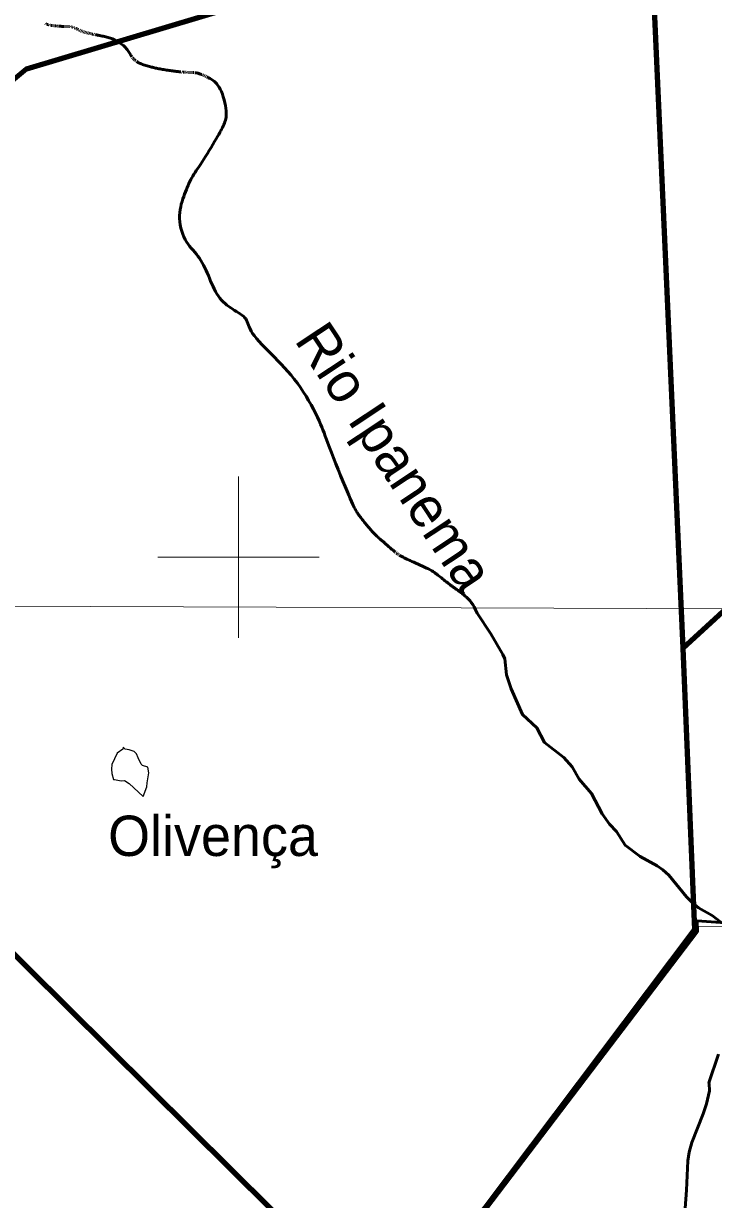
# Model space of a CAD drawing. Extents: x -1643653 to 4543381, y 1624270 to 13878484.
# Drawn here: x 697335 to 705888, y 8942036 to 8956618 of the extents above; entities that cross this region are included whole.
import ezdxf
from ezdxf.enums import TextEntityAlignment as Align

# ---------------------------------------------------------------- set-up
doc = ezdxf.new("R2010")
doc.units = 0
doc.header["$LTSCALE"] = 200
for name, color, linetype, lineweight in [('1', 7, 'Continuous', 13), ('2', 7, 'Continuous', 13), ('21', 7, 'Continuous', 25), ('24', 7, 'Continuous', 25), ('58', 7, 'Continuous', 13), ('59', 7, 'Continuous', 53), ('60', 7, 'Continuous', 13), ('9', 7, 'Continuous', 90)]:
    doc.layers.add(name, color=color, linetype=linetype, lineweight=lineweight)
doc.layers.add('41', color=7, linetype='Continuous')
doc.layers.add('49', color=7, linetype='Continuous')

msp = doc.modelspace()

# ---------------------------------------------------------------- linework, layer by layer
at = {"layer": '1'}
msp.add_line((565315.3, 8949866.8), (791497.7, 8949052.2), dxfattribs=at)
at = {"layer": '2'}
for p, q in [((700000, 8949000), (700000, 8951000)), ((699000, 8950000), (701000, 8950000))]:
    msp.add_line(p, q, dxfattribs=at)
at = {"layer": '21'}
for points in [[(698875, 8947397.9), (698811.7, 8947415.6), (698794.2, 8947433.6), (698754.7, 8947514.3), (698737.5, 8947564.1), (698706.2, 8947592.7), (698643, 8947613), (698593.3, 8947619.9), (698571.6, 8947643.2), (698565.2, 8947619.3), (698494.7, 8947572.1), (698431.7, 8947429.7), (698426.6, 8947373.4), (698428.3, 8947318.5), (698449.3, 8947244.8)], [(698819.7, 8947032.6), (698863.9, 8947152.1), (698866.6, 8947202.8), (698888.3, 8947328.1), (698875, 8947397.9)], [(698449.3, 8947244.8), (698461.1, 8947244.4), (698543.5, 8947225.9), (698588, 8947231.3), (698646.7, 8947194.3), (698819.7, 8947032.6)]]:
    msp.add_lwpolyline(points, dxfattribs=at)
at = {"layer": '24', "lineweight": 53}
for p, q in [((697613.6, 8956613.2), (697607.7, 8956616.2)), ((697624.7, 8956608.1), (697619.3, 8956610.5)), ((697635.2, 8956604.2), (697630, 8956606)), ((697645.8, 8956601.1), (697640.4, 8956602.6)), ((697657.3, 8956598.6), (697651.4, 8956599.8)), ((697670.7, 8956596.3), (697663.7, 8956597.5)), ((697685.8, 8956594), (697678.1, 8956595.1)), ((697701.9, 8956591.7), (697693.8, 8956592.8)), ((697718.2, 8956589.7), (697710.1, 8956590.7)), ((697733.7, 8956587.9), (697726.1, 8956588.8)), ((697748.3, 8956586.4), (697741.1, 8956587.1)), ((697762.1, 8956585.1), (697755.3, 8956585.7)), ((697775.3, 8956584.2), (697768.8, 8956584.6)), ((697788.1, 8956583.5), (697781.8, 8956583.8)), ((697800.7, 8956583.1), (697794.4, 8956583.3)), ((697812.9, 8956582.8), (697806.8, 8956582.9)), ((697824.9, 8956582.7), (697818.9, 8956582.8)), ((697836.6, 8956582.6), (697830.8, 8956582.7)), ((697848, 8956582.5), (697842.3, 8956582.6)), ((697859, 8956582.4), (697853.5, 8956582.5)), ((697869.5, 8956582.3), (697864.3, 8956582.4)), ((697879.6, 8956582.2), (697874.6, 8956582.3)), ((697894, 8956581.8), (697889.2, 8956582)), ((697908.8, 8956580.5), (697903.7, 8956581.1)), ((697919.3, 8956578.7), (697914, 8956579.7)), ((697930.7, 8956576.1), (697924.9, 8956577.5)), ((697942.6, 8956572.7), (697936.6, 8956574.5)), ((697955, 8956568.4), (697948.8, 8956570.6)), ((697967.8, 8956563.3), (697961.4, 8956565.9)), ((697980.9, 8956557.4), (697974.3, 8956560.4)), ((697994.3, 8956551), (697987.6, 8956554.3)), ((698008.2, 8956544.3), (698001.2, 8956547.7)), ((698022.7, 8956537.6), (698015.4, 8956541)), ((698037.7, 8956530.8), (698030.1, 8956534.2)), ((698053.2, 8956524.3), (698045.4, 8956527.5)), ((698069.3, 8956518.1), (698061.2, 8956521.1)), ((698086, 8956512.4), (698077.6, 8956515.2)), ((698102.9, 8956507.2), (698094.4, 8956509.7)), ((698119.7, 8956502.6), (698111.4, 8956504.8)), ((698135.9, 8956498.6), (698127.9, 8956500.5)), ((698150.9, 8956495.1), (698143.5, 8956496.8)), ((698165.1, 8956492.1), (698158, 8956493.5)), ((698179.3, 8956489.1), (698172.1, 8956490.6)), ((698194.5, 8956486.1), (698186.7, 8956487.6)), ((698211.8, 8956482.6), (698202.9, 8956484.4)), ((698231.6, 8956478.5), (698221.4, 8956480.6)), ((698690.6, 8956189.2), (698684.8, 8956196.3)), ((698702.1, 8956176.5), (698696.3, 8956182.6)), ((698714.2, 8956165.1), (698708, 8956170.8)), ((698727.8, 8956153.9), (698720.8, 8956159.5)), ((699306.4, 8956015.8), (699297.1, 8956016.8)), ((699323.6, 8956014.3), (699315.3, 8956015)), ((699338.8, 8956013.3), (699331.4, 8956013.7)), ((699352.6, 8956012.7), (699345.9, 8956013)), ((699365.2, 8956012.5), (699359, 8956012.6)), ((699377.1, 8956012.3), (699371.2, 8956012.4)), ((699388.8, 8956012.2), (699382.9, 8956012.3)), ((699400.9, 8956012), (699394.7, 8956012.1)), ((699414.3, 8956011.4), (699407.4, 8956011.7)), ((699429.8, 8956010.4), (699421.8, 8956011)), ((699447.7, 8956008.8), (699438.5, 8956009.7)), ((699564.3, 8955975.6), (699555.5, 8955979.7)), ((699581.7, 8955967.5), (699573.1, 8955971.5)), ((699599, 8955959.6), (699590.3, 8955963.6)), ((701961.4, 8950050), (701954.2, 8950055.7)), ((701974.9, 8950039.7), (701968.2, 8950044.7)), ((701989, 8950029.7), (701981.8, 8950034.7))]:
    msp.add_line(p, q, dxfattribs=at)
for points in [[(698678.9, 8956204.2), (698672.8, 8956212.9), (698666.4, 8956222.7), (698659.6, 8956233.6), (698652.4, 8956245.5), (698644.6, 8956258), (698636.4, 8956270.9), (698627.6, 8956284.1), (698618.2, 8956297.2), (698608.1, 8956309.9), (698597.4, 8956322.1), (698586.1, 8956333.4), (698574.2, 8956344.1), (698561.9, 8956353.9), (698549.4, 8956363.1), (698536.9, 8956371.7), (698524.5, 8956379.7), (698512.4, 8956387.2), (698500.7, 8956394.2), (698489.7, 8956400.8), (698479, 8956406.9), (698468.5, 8956412.8), (698458.1, 8956418.2), (698447.4, 8956423.4), (698436.3, 8956428.3), (698424.5, 8956432.9), (698412, 8956437.3), (698398.4, 8956441.5), (698384.1, 8956445.5), (698369.1, 8956449.3), (698353.8, 8956452.9), (698338.3, 8956456.4), (698322.9, 8956459.7), (698307.9, 8956462.8), (698293.3, 8956465.8), (698279.5, 8956468.6), (698266.5, 8956471.3), (698254.2, 8956473.8), (698242.5, 8956476.2), (698231.6, 8956478.5)], [(698752.2, 8956137.3), (698743.4, 8956142.8), (698735.2, 8956148.3)], [(699287.1, 8956017.8), (699276.6, 8956019), (699265.5, 8956020.3), (699253.7, 8956021.7), (699241.2, 8956023.2), (699228.1, 8956024.7), (699214.3, 8956026.3), (699200, 8956028.1), (699185.2, 8956029.9), (699170, 8956031.8), (699154.4, 8956033.8), (699138.5, 8956036), (699122.5, 8956038.3), (699106.3, 8956040.7), (699090.1, 8956043.3), (699073.9, 8956046), (699057.9, 8956048.7), (699042.2, 8956051.5), (699026.9, 8956054.4), (699012.1, 8956057.3), (698997.8, 8956060.2), (698984.3, 8956063.1), (698971.2, 8956066), (698958.5, 8956069), (698946, 8956072), (698933.6, 8956075.2), (698921, 8956078.5), (698908.1, 8956081.9), (698894.8, 8956085.6), (698880.9, 8956089.4), (698866.6, 8956093.5), (698852.1, 8956097.7), (698837.6, 8956102.1), (698823.2, 8956106.7), (698809.4, 8956111.5), (698796.1, 8956116.4), (698783.7, 8956121.4), (698772.2, 8956126.6), (698761.8, 8956131.9), (698752.2, 8956137.3)], [(699546.5, 8955983.8), (699537.3, 8955987.7), (699527.9, 8955991.4), (699518.3, 8955994.8), (699508.4, 8955997.8), (699498.3, 8956000.5), (699488, 8956002.8), (699477.7, 8956004.7), (699467.5, 8956006.4), (699457.4, 8956007.7)], [(699780.5, 8955289.2), (699791.1, 8955309.7), (699800.6, 8955328.8), (699809.3, 8955347), (699817.2, 8955364.7), (699824.6, 8955382.1), (699831.3, 8955399.8), (699837.2, 8955418.2), (699841.9, 8955437.6), (699845.4, 8955458.6), (699847.4, 8955481.6), (699847.7, 8955507), (699846.2, 8955535.2), (699842.7, 8955566.6), (699837.2, 8955600.3), (699830.1, 8955635.5), (699821.4, 8955671.3), (699811.2, 8955706.8), (699799.9, 8955741.1), (699787.5, 8955773.3), (699774.2, 8955802.5), (699760.2, 8955828), (699745.7, 8955850), (699730.8, 8955868.8), (699715.9, 8955884.8), (699701.2, 8955898.2), (699686.8, 8955909.6), (699673.1, 8955919.3), (699660.1, 8955927.5), (699648.2, 8955934.6), (699637.1, 8955940.8), (699626.8, 8955946.3), (699617.1, 8955951.1), (699607.8, 8955955.6)], [(699278.7, 8954120.9), (699273.4, 8954159.9), (699270.6, 8954198.8), (699270.2, 8954237.1), (699272.4, 8954274.3), (699276.9, 8954310.4), (699283.3, 8954345.4), (699291.3, 8954379.3), (699300.5, 8954412.1), (699310.6, 8954443.7), (699321.3, 8954474.3), (699332.1, 8954503.7), (699342.9, 8954532), (699353.6, 8954559.3), (699364.3, 8954585.6), (699375.2, 8954611), (699386.3, 8954635.6), (699397.6, 8954659.4), (699409.3, 8954682.5), (699421.5, 8954704.9), (699434.3, 8954726.9), (699447.7, 8954748.7), (699461.9, 8954770.9), (699477, 8954793.8), (699493.1, 8954818), (699510.4, 8954843.8), (699528.9, 8954871.7), (699548.8, 8954902.1), (699570.1, 8954935.3), (699592.4, 8954970.7), (699615.3, 8955007.6), (699638.3, 8955045.1), (699661.1, 8955082.6), (699683, 8955119.1), (699703.8, 8955154), (699722.8, 8955186.5), (699739.9, 8955216), (699755.1, 8955242.7), (699768.5, 8955267), (699780.5, 8955289.2)], [(699976.1, 8953045.1), (699952.3, 8953059.7), (699928.3, 8953074.9), (699904.2, 8953090.9), (699880.4, 8953107.7), (699857, 8953125.7), (699834.1, 8953144.9), (699811.8, 8953165.5), (699790.4, 8953187.8), (699769.9, 8953211.7), (699750.6, 8953237.6), (699732.5, 8953265.5), (699715.5, 8953295.1), (699699.4, 8953326.2), (699684.1, 8953358.4), (699669.3, 8953391.4), (699654.9, 8953424.8), (699640.7, 8953458.5), (699626.5, 8953491.9), (699612.2, 8953524.9), (699597.7, 8953557.3), (699582.7, 8953589), (699567.2, 8953619.9), (699551.1, 8953649.9), (699534.2, 8953678.8), (699516.5, 8953706.6), (699497.7, 8953733.1), (699477.8, 8953758.4), (699457.2, 8953782.8), (699436.2, 8953806.9), (699415.1, 8953831.2), (699394.3, 8953856.1), (699374.3, 8953882.2), (699355.3, 8953910.1), (699337.8, 8953940.1), (699322, 8953972.8), (699308, 8954007.6), (699296.1, 8954044.2), (699286.3, 8954082.2), (699278.7, 8954120.9)], [(701016.4, 8951651.8), (700998.5, 8951692.1), (700977.8, 8951736.6), (700954.4, 8951784.7), (700928.4, 8951835.6), (700900.1, 8951888.6), (700869.6, 8951943), (700837.1, 8951997.8), (700802.8, 8952052.4), (700766.9, 8952105.9), (700729.6, 8952157.8), (700691, 8952207.9), (700651.4, 8952256.4), (700611, 8952303.5), (700570.1, 8952349.2), (700528.7, 8952393.8), (700487.3, 8952437.2), (700445.8, 8952479.6), (700404.8, 8952521.2), (700364.6, 8952561.8), (700325.9, 8952601.2), (700289.2, 8952639.2), (700255.2, 8952675.8), (700224.5, 8952710.6), (700197.6, 8952743.6), (700175.2, 8952774.6), (700157.5, 8952803.5), (700143.9, 8952830.2), (700133.3, 8952855.1), (700124.7, 8952878.2), (700117, 8952899.6), (700109.4, 8952919.6), (700100.7, 8952938.1), (700089.9, 8952955.5), (700076.3, 8952971.8), (700060.1, 8952987.2), (700041.5, 8953002.1), (700021.1, 8953016.5), (699999.1, 8953030.8), (699976.1, 8953045.1)], [(701583.5, 8950407.2), (701573.5, 8950419.6), (701563.5, 8950432.1), (701553.6, 8950444.4), (701543.7, 8950456.7), (701534.2, 8950468.7), (701524.9, 8950480.3), (701516.1, 8950491.5), (701507.8, 8950502.2), (701500.1, 8950512.3), (701492.9, 8950522), (701486, 8950531.6), (701479.4, 8950541.3), (701472.8, 8950551.4), (701466.1, 8950562.2), (701459.3, 8950573.8), (701452.1, 8950586.6), (701444.4, 8950600.9), (701435.8, 8950617.5), (701426.1, 8950637.4), (701414.8, 8950661.5), (701401.5, 8950690.8), (701385.9, 8950726.3), (701367.7, 8950768.7), (701346.4, 8950819.2), (701321.9, 8950878.1), (701294.9, 8950943.8), (701266.2, 8951014.1), (701236.8, 8951086.9), (701207.5, 8951160.1), (701179.1, 8951231.5), (701152.6, 8951298.9), (701128.9, 8951360.2), (701108.5, 8951413.9), (701090.9, 8951461), (701075.3, 8951502.9), (701060.9, 8951541.4), (701046.8, 8951578), (701032.2, 8951614.2), (701016.4, 8951651.8)], [(701946.4, 8950061.9), (701938.1, 8950068.5), (701929.4, 8950075.4), (701920.4, 8950082.7), (701911.2, 8950090.2), (701901.9, 8950097.8), (701892.6, 8950105.7), (701883.4, 8950113.5), (701874.3, 8950121.4), (701865.5, 8950129.2), (701856.9, 8950137), (701848.4, 8950144.6), (701840.2, 8950152.2), (701832, 8950159.5), (701824.1, 8950166.6), (701816.3, 8950173.5), (701808.6, 8950180.1), (701800.9, 8950186.6), (701793.2, 8950193.1), (701785.4, 8950199.6), (701777.3, 8950206.3), (701768.9, 8950213.4), (701760, 8950220.9), (701750.6, 8950229), (701740.7, 8950237.8), (701730.2, 8950247.2), (701719.3, 8950257.2), (701708.2, 8950267.6), (701697, 8950278.3), (701685.8, 8950289.4), (701674.6, 8950300.8), (701663.7, 8950312.2), (701653.1, 8950323.8), (701642.8, 8950335.4), (701632.7, 8950347.1), (701622.8, 8950358.9), (701612.9, 8950370.8), (701603.2, 8950382.8), (701593.4, 8950395), (701583.5, 8950407.2)], [(702375.5, 8949843.3), (702354.4, 8949854.7), (702331.2, 8949866.5), (702306.2, 8949878.5), (702280.1, 8949890.7), (702253.3, 8949902.8), (702226.3, 8949914.8), (702199.6, 8949926.5), (702173.8, 8949937.8), (702149.4, 8949948.6), (702126.7, 8949958.8), (702105.9, 8949968.3), (702086.8, 8949977.3), (702069.4, 8949985.7), (702053.6, 8949993.5), (702039.4, 8950000.7), (702026.7, 8950007.4), (702015.5, 8950013.6), (702005.6, 8950019.3), (701996.8, 8950024.7)], [(702959.4, 8949306.4), (702939.6, 8949349.7), (702920.8, 8949385.8), (702903, 8949415.8), (702886.1, 8949440.6), (702870, 8949461), (702854.7, 8949478), (702839.9, 8949492.5), (702825.7, 8949505.3), (702812, 8949517.4), (702798.5, 8949528.8), (702785.4, 8949539.8), (702772.4, 8949550.3), (702759.4, 8949560.5), (702746.4, 8949570.5), (702733.2, 8949580.3), (702719.8, 8949590.2), (702706.1, 8949600.1), (702692.1, 8949610.1), (702677.8, 8949620.2), (702663.2, 8949630.5), (702648.6, 8949641), (702633.8, 8949651.6), (702618.8, 8949662.5), (702603.9, 8949673.6), (702589, 8949685), (702574.1, 8949696.6), (702559.2, 8949708.4), (702544.4, 8949720.2), (702529.7, 8949732), (702515.2, 8949743.7), (702500.8, 8949755.3), (702486.6, 8949766.7), (702472.5, 8949777.8), (702458.4, 8949788.8), (702443.8, 8949799.6), (702428.6, 8949810.4), (702412.3, 8949821.2), (702394.7, 8949832.2), (702375.5, 8949843.3)], [(705978.7, 8945474.4), (705872.5, 8945557.9), (705704.5, 8945652.5), (705622.4, 8945719.5), (705553.2, 8945790.5), (705334.1, 8946058.7), (705261.1, 8946123.8), (705190.9, 8946173.3), (704977.8, 8946288.6), (704792.6, 8946429), (704685.4, 8946600), (704597.4, 8946688.7), (704507.1, 8946819.4), (704375.5, 8947069.7), (704224.8, 8947248.3), (704136.7, 8947399.1), (704032, 8947515), (703791.7, 8947704), (703699.7, 8947883.2), (703521.3, 8948048.6), (703380.4, 8948367.8), (703323, 8948543.7), (703301.3, 8948739.4), (703276.6, 8948792.4), (703126.8, 8949051.7), (702959.4, 8949306.4)], [(705832.8, 8943474.1), (705832.2, 8943483.4), (705948.7, 8943839)], [(705536.3, 8941930.6), (705555.5, 8942152.9), (705571.3, 8942515.6), (705588.8, 8942621.5), (705620.6, 8942742.3), (705760.4, 8943097.5), (705802.3, 8943224.2), (705838.5, 8943384.3), (705832.8, 8943474.1)]]:
    msp.add_lwpolyline(points, dxfattribs=at)
at = {"layer": '58'}
msp.add_lwpolyline([(721735.1, 8945462.2), (705687.3, 8945423), (701918.9, 8940389.2), (702367, 8940066.2), (702236.6, 8939350.5), (702436.4, 8938315), (702230.8, 8937763), (702061.8, 8937174.3), (696166.5, 8937724.4), (694006.3, 8932846.6), (690630.4, 8932391.1), (689144, 8929202.5)], dxfattribs=at)
at = {"layer": '59'}
msp.add_lwpolyline([(701918.9, 8940389.2), (705690.1, 8945354.7), (705684.5, 8945491.4)], dxfattribs=at)
msp.add_spline([(705684.5, 8945491.4), (706613.6, 8945433), (713159.8, 8945469.6), (721577.7, 8945460.4), (723248, 8945520.1)], degree=3, dxfattribs=at)
at = {"layer": '60', "lineweight": 25}
msp.add_spline([(814781, 9009175.5), (814787.2, 9009173.4), (814796.9, 9009173.4), (814799.4, 9009172.4), (814805.1, 9009174.5), (814805.6, 9009176.5), (814811.7, 9009179.5), (814811.7, 9009179.5), (814801.5, 9009181), (814790.7, 9009181.5), (814784.1, 9009183.1), (814777.4, 9009185.1), (814778.4, 9009175.5)], degree=3, dxfattribs=at)
at = {"layer": '9'}
for points in [[(691582, 8951218.7), (697371.2, 8956056), (705081.2, 8958366.8), (713138.6, 8969695)], [(705081.2, 8958366.8), (705509.2, 8948874.2), (720755.9, 8962863.6), (723053.6, 8963740.6)], [(705509.2, 8948874.2), (705653.5, 8945380.8), (701918.9, 8940415.3), (694874, 8947402.7)]]:
    msp.add_lwpolyline(points, dxfattribs=at)

# ---------------------------------------------------------------- texts
at = {"layer": '41'}
msp.add_text('Olivença', height=500, dxfattribs=at).set_placement((698383.7, 8946295.8))
at = {"layer": '49'}
msp.add_text('Rio Ipanema', height=500, rotation=303.53, dxfattribs=at).set_placement((701731.3, 8951111.3), align=Align.CENTER)

doc.saveas('drawing.dxf')
